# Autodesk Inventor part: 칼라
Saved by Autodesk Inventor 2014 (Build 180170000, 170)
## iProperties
Created: 2026-01
Part Number: 칼라
Material: 일반
Document SubType Name: Modeling
Designer: dg
Density: 1 g/cm^3
Appearance: 기본값
Author: dg
Author: jhkim
Creation Date: 2026-01-09
Sending System: Autodesk Inventor 2026
Preprocessor: ST-DEVELOPER v20.1
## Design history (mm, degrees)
node "칼라1"
node "솔리드1"
node "기준1"
